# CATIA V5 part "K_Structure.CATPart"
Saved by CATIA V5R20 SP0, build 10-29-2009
Part number: Structure
Property "Longueur_structure": 200 mm
Publications: "epaisseur_struct", "hauteur_struct", "diamètre_liaison_struct_bras"
Bounding box of the stored display mesh (mm): x -97 to 20, y -121.066 to 142.274, z -121.064 to 142.274
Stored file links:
  G:\Khaled_CFAO_2011\ST2M\ST2M_GR2\plakomicki\Khaled\CAD_ThinkMOTION\K_Structure.CATPart
  G:\Khaled_CFAO_2011\ST2M\ST2M_GR2\plakomicki\Khaled\CAD_ThinkMOTION\K_Jambe.CATProduct
  G:\Khaled_CFAO_2011\ST2M\ST2M_GR2\plakomicki\Khaled\plakomicki\Squelette_bras.CATPart
  G:\Khaled_CFAO_2011\ST2M\ST2M_GR2\plakomicki\Khaled\CAD_ThinkMOTION\K_Bras.CATPart
  G:\Khaled_CFAO_2011\ST2M\ST2M_GR2\plakomicki\Khaled\CAD_ThinkMOTION\K_Squel_Jambe.CATPart
  G:\Khaled_CFAO_2011\ST2M\ST2M_GR2\plakomicki\Khaled\CAD_ThinkMOTION\K_Balancier.CATPart
  G:\Khaled_CFAO_2011\ST2M\ST2M_GR2\plakomicki\Khaled\CAD_ThinkMOTION\K_Bielle_liaison.CATPart
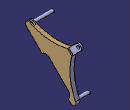
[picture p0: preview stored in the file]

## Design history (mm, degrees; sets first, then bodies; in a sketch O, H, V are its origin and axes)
Parameters
  epaisseur_struct = 20 mm
  hauteur_struct = 130 mm
  `diamètre_liaison_struct_bras` = 15 mm
External parameters (linked from other documents)
  External.Longueur_structure = 300 mm
  External.diametre_exterieure_roue = 200 mm
Set1
  Plane1: linked copy from another document
  Point1 "Point_struct_bras": linked copy from another document
  Point2 "Point_struct_balancier": linked copy from another document
  Line1 "axe_pivot_struct_bras": linked copy from another document
  Plane2: linked copy from another document
  Plane3: linked copy from another document
  Point3: linked copy from another document
  Point4: linked copy from another document
  Plane4: linked copy from another document
  Plane5 "Plan_pivot_struct_bras": linked copy from another document
  DatumSurface1 to DatumSurface3: linked copy from another document
Body1 (main body)
  Sketch1 on Plane1, origin (0, 0, 0), H (0, 1, 0), V (0, 0, 1)
    arc A1 centre (-106.066, 106.066) radius 15 from (-99.531, 119.5676) to (-116.6726, 95.4594) ccw
    point P1 (-106.066, 106.066)
    arc A2 centre (106.066, -106.066) radius 15 from (95.4594, -116.6726) to (119.5676, -99.531) ccw
    point P2 (106.066, -106.066)
    reference projected point E1 (106.066, -106.066) from Point2
    circle A3 centre (-106.066, 106.066) radius 7.5
    circle A4 centre (106.066, -106.066) radius 7.5
    line L1 (-116.6726, 95.4594) -> (95.4594, -116.6726)
    point P5 (0, 0)
    line L2 (81.3173, 102.5305) -> (102.5305, 81.3173)
    point P8 (81.3173, 102.5305)
    point P9 (102.5305, 81.3173)
    reference projected point E2 (0, 0) from Point4
    point P10 (106.066, -106.066)
    arc A5 centre (13.7427, 353.5956) radius 260 from (-99.531, 119.5676) to (81.3173, 102.5305) ccw
    point P12 (81.3173, 102.5305)
    axis line L3 (0, 0) -> (98.2791, 98.2791)
    arc A6 centre (353.5956, 13.7427) radius 260 from (102.5305, 81.3173) to (119.5676, -99.531) ccw
    point P14 (353.5956, 13.7427)
    point P15 (102.5305, 81.3173)
    reference projected point E3 (-106.066, 106.066) from Point1
    reference projected point E4 (106.066, -106.066) from Point2
    radius A1 = 15
    radius A2 = 15
    radius A3 = 7.5 {= `diamètre_liaison_struct_bras` /2}
    radius A4 = 7.5
    distance P2 P5 = 150 {= `détruit_rapport_distance_hauteur_longueur` *External.Longueur_structure}
    distance E2 L2 = 130 {= hauteur_struct}
    length L2 = 30
    distance L3 P8 = 15
    angle H L3 = 45
    radius A5 = 260 {= hauteur_struct *2}
    distance P14 A6 = 260 {= hauteur_struct *2}
    coincidence: P2 E1, P12 L2, P12 P8, P15 L2, P15 P9, P1 E3, E4 P2
    tangency: L1 A1, L1 A2, A6 A2, A5 A1
    concentricity: P10 A4
    perpendicularity: L3 L2
  Pad1: profile Sketch1, direction (1, 0, 0), length 20 {= epaisseur_struct}
  Sketch2 on face of Pad1, origin (20, 0, 0), H (0, 1, 0), V (0, 0, 1)
    construction line L1 (-23.5833, 2.3701) -> (67.3414, -88.5546)
    point P2 (67.3414, -88.5546)
    line L2 (-5.9056, 20.0477) -> (85.019, -70.8769)
    line L3 (49.6637, -106.2322) -> (-41.2609, -15.3076)
    arc A1 centre (67.3414, -88.5546) radius 25 from (85.019, -70.8769) to (49.6637, -106.2322) cw
    arc A2 centre (-23.5833, 2.3701) radius 25 from (-41.2609, -15.3076) to (-5.9056, 20.0477) cw
    reference projected line E1 (-116.6726, 95.4594) -> (95.4594, -116.6726) from edge [face of Pad1 from Sketch1.L1 | end face of Pad1]
    reference projected circle E2 centre (106.066, -106.066) radius 7.5 from edge [end face of Pad1 | face of Pad1 from Sketch1.A4]
    reference projected circle E3 centre (-106.066, 106.066) radius 7.5 from edge [end face of Pad1 | face of Pad1 from Sketch1.A3]
    distance L1 L2 = 25
    distance P2 E2 = 50
    distance A2 E3 = 100
    tangency: A1 L2, A2 L2, A1 L3, A2 L3
    coincidence: L1 E1
  Pocket1: profile Sketch2, direction (-1, 0, 0), up to start face of Pad1
  Sketch3 on face of Pad1, origin (20, 0, 0), H (0, 1, 0), V (0, 0, 1)
    axis line L1 (0, 0) -> (103.8647, 103.8647)
    arc A1 centre (127.2792, 127.2792) radius 15 from (137.8858, 116.6726) to (116.6726, 137.8858) ccw
    point P2 (127.2792, 127.2792)
    circle A2 centre (127.2792, 127.2792) radius 7.5
    line L2 (116.6726, 137.8858) -> (81.3173, 102.5305)
    line L3 (137.8858, 116.6726) -> (102.5305, 81.3173)
    line L4 (81.3173, 102.5305) -> (102.5305, 81.3173)
    angle L1 H = 45
    radius A1 = 15 {= `diamètre_liaison_struct_bras`}
    radius A2 = 7.5 {= `diamètre_liaison_struct_bras` /2}
    distance O P2 = 180 {= hauteur_struct +50mm}
    distance L4 O = 130 {= hauteur_struct}
    coincidence: L1 P2
    tangency: L2 A1, L3 A1
    perpendicularity: L4 L2
    parallelism: L2 L3, L1 L3
  Pad2: profile Sketch3, direction (-1, 0, 0), length 14 {= (epaisseur_struct )/2+4mm}, opposite side length -6 {= -(epaisseur_struct) /2+4mm}
  Sketch4 on face of Pad1, origin (20, 0, 0), H (0, 1, 0), V (0, 0, 1)
    circle A1 centre (106.066, -106.066) radius 7.5
    point P1 (106.066, -106.066)
    reference projected point E1 (106.066, -106.066) from Point2
    radius A1 = 7.5
    coincidence: P1 E1
  Pad3: profile Sketch4, direction (1, 0, 0), up to face of DatumSurface2
  Sketch5 on end face of Pad1, origin (20, 0, 0), H (0, 1, 0), V (0, 0, 1)
    circle A1 centre (-106.066, 106.066) radius 7.5
    point P1 (-106.066, 106.066)
    reference projected point E1 (-106.066, 106.066) from Line1
    radius A1 = 7.5 {= `diamètre_liaison_struct_bras` /2}
    coincidence: P1 E1
  Pad4: profile Sketch5, direction (1, 0, 0), up to face of DatumSurface3, opposite side up to face of Pad1
  Sketch6 on face of Pad1 from Sketch1.L1, origin (0, -10.6066, -10.6066), H (1, 0, 0), V (0, -0.7071, 0.7071)
    line L1 (6, 140) -> (14, 140)
    line L2 (14, 140) -> (14, 165)
    line L3 (14, 165) -> (6, 165)
    line L4 (6, 165) -> (6, 140)
    reference projected line E1 (-87, 150) -> (87, 150) from Line1
    reference projected line E2 (-87, 150) -> (87, 150) from Line1
    reference projected line E3 (-87, 150) -> (87, 150) from Line1
    reference projected line E4 (-87, 150) -> (87, 150) from Line1
    reference projected line E5 (0, 150) -> (0, -150) from edge [start face of Pad1 | face of Pad1 from Sketch1.L1]
    length L1 = 8
    distance E1 L1 = 10
    distance E2 E3 = 0 (reference)
    distance E4 L3 = 15
    distance E5 L4 = 6 {= epaisseur_struct /2-4mm}
    horizontal: L1 H, L3 H
    vertical: L2 V, L4 V
  Pocket2: profile Sketch6, direction (0, 0.7071, 0.7071), up to face of Pad1 from Sketch1.A1
  Pad5: profile Sketch5, direction (-1, 0, 0), up to face of Pocket2 from Sketch6.L4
